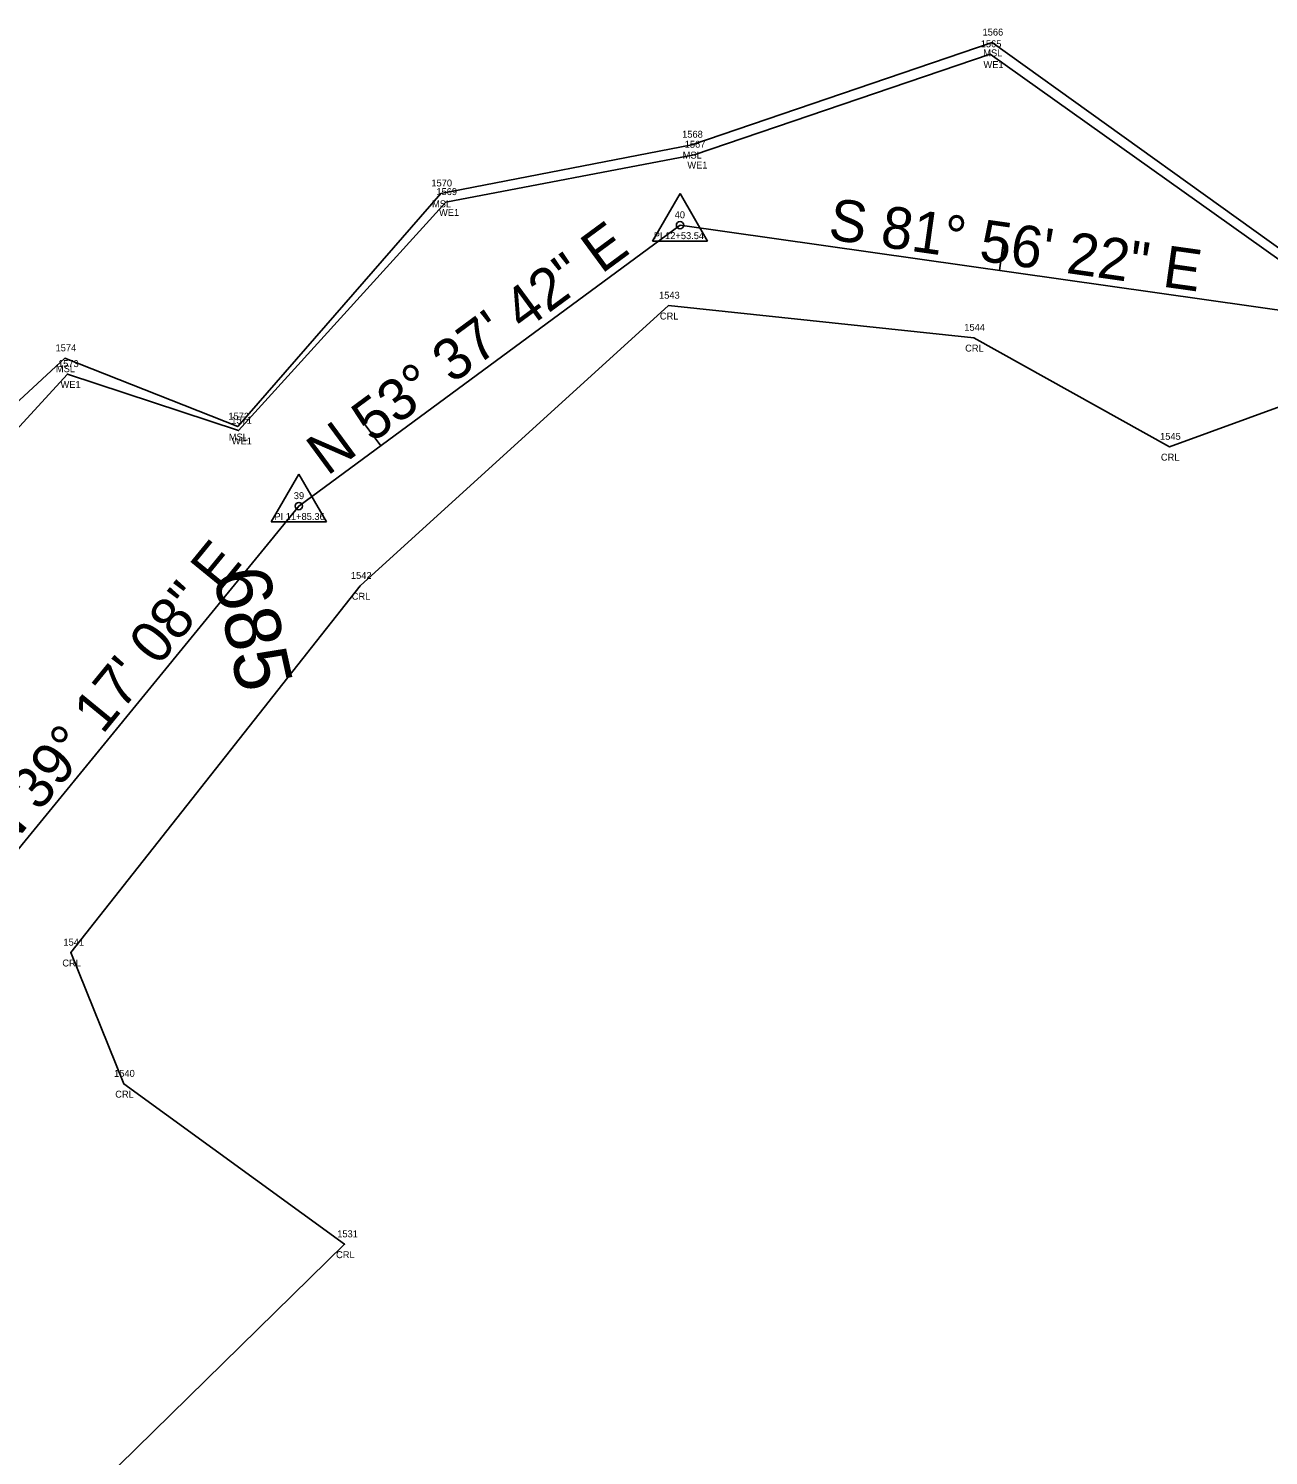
# Model space of a CAD drawing. Extents: x 2521558 to 2524785, y 882711 to 887632.
# Drawn here: x 2523844.7 to 2524023.3, y 885124.5 to 885330 of the extents above; entities that cross this region are included whole.
import ezdxf

# ---------------------------------------------------------------- set-up
doc = ezdxf.new("R2010")
doc.units = 0
for name, color, linetype in [('RD_EX_H2O', 7, 'Continuous'), ('RD_EX_H2O_txCode', 7, 'Continuous'), ('RD_EX_Misc', 7, 'Continuous'), ('RD_EX_Misc_txCode', 7, 'Continuous'), ('RD_HC_Cl', 7, 'Continuous'), ('RD_HC_Data', 7, 'Continuous'), ('RD_HC_Data_Tic', 7, 'Continuous'), ('RD_HC_TX_Sta50', 7, 'Continuous'), ('RD_HC_txCode', 7, 'Continuous'), ('RD_SMD_Locator', 7, 'Continuous')]:
    doc.layers.add(name, color=color, linetype=linetype)

msp = doc.modelspace()

# ---------------------------------------------------------------- linework, layer by layer
at = {"layer": 'RD_EX_H2O'}
for points in [[(2524064.86, 885165.15), (2524036.37, 885213.78), (2524057.22, 885252.72), (2524031.95, 885291.63), (2523983.25, 885326.3), (2523940.61, 885311.83), (2523904.84, 885305.01), (2523874.98, 885272.1), (2523850.32, 885280.24), (2523830.66, 885258.8), (2523826.93, 885206.61)], [(2523582.82, 884766.34), (2523598.11, 884856.98), (2523627.59, 884901.75), (2523623.76, 884928.28), (2523586.58, 884955.43), (2523600.94, 884974.12), (2523633.05, 884997.68), (2523679.17, 885037.05), (2523744.72, 885076.89), (2523769.38, 885099), (2523825.47, 885108.66), (2523825.47, 885108.66), (2523845.24, 885110.83), (2523890.25, 885154.93), (2523858.43, 885178.04), (2523850.81, 885196.93), (2523892.51, 885249.74), (2523936.89, 885290.09), (2523980.86, 885285.47), (2524009.06, 885269.77), (2524037.39, 885280.09)]]:
    msp.add_lwpolyline(points, dxfattribs=at)
at = {"layer": 'RD_EX_Misc'}
msp.add_lwpolyline([(2524066.31, 885165.35), (2524037.3, 885214.15), (2524057.95, 885253.07), (2524039.52, 885283.17), (2524032.92, 885292.57), (2523983.53, 885327.98), (2523940.24, 885313.27), (2523904.13, 885306.25), (2523874.86, 885272.67), (2523849.96, 885282.51), (2523827.65, 885261.93), (2523821.38, 885209.28)], dxfattribs=at)
at = {"layer": 'RD_HC_Cl'}
for p, q in [((2523883.66, 885261.23), (2523938.56, 885301.67)), ((2523938.56, 885301.67), (2524036.25, 885287.83)), ((2523836.11, 885203.1), (2523883.66, 885261.23))]:
    msp.add_line(p, q, dxfattribs=at)
at = {"layer": 'RD_HC_Data'}
for p, q in [((2523934.59, 885299.37), (2523938.56, 885306.25)), ((2523938.56, 885306.25), (2523942.53, 885299.37)), ((2523934.59, 885299.37), (2523942.53, 885299.37)), ((2523879.69, 885258.94), (2523883.66, 885265.82)), ((2523883.66, 885265.82), (2523887.63, 885258.94)), ((2523879.69, 885258.94), (2523887.63, 885258.94))]:
    msp.add_line(p, q, dxfattribs=at)
for centre in [(2523938.56, 885301.67), (2523883.66, 885261.23)]:
    msp.add_circle(centre, 0.529, dxfattribs=at)
at = {"layer": 'RD_HC_Data_Tic'}
for p, q in [((2523984.56, 885295.15), (2523985.12, 885299.11)), ((2523895.45, 885269.91), (2523893.08, 885273.13))]:
    msp.add_line(p, q, dxfattribs=at)
at = {"layer": 'RD_SMD_Locator'}
for centre in [(2523983.53, 885327.98), (2523983.25, 885326.3), (2523940.24, 885313.27), (2523940.61, 885311.83), (2523904.13, 885306.25), (2523904.84, 885305.01), (2523938.56, 885301.67), (2523936.89, 885290.09), (2523980.86, 885285.47), (2523849.96, 885282.51), (2523850.32, 885280.24), (2523874.86, 885272.67), (2523874.98, 885272.1), (2524009.06, 885269.77), (2523883.66, 885261.23), (2523892.51, 885249.74), (2523850.81, 885196.93), (2523858.43, 885178.04), (2523890.25, 885154.93)]:
    msp.add_circle(centre, 0.001, dxfattribs=at)

# ---------------------------------------------------------------- texts
at = {"layer": 'RD_EX_H2O_txCode'}
for s, p in [('1565', (2523981.88, 885327.3)), ('WE1', (2523982.27, 885324.3)), ('1567', (2523939.24, 885312.83)), ('WE1', (2523939.62, 885309.83)), ('1569', (2523903.47, 885306.01)), ('WE1', (2523903.85, 885303.01)), ('1543', (2523935.54, 885291.09)), ('CRL', (2523935.66, 885288.09)), ('1544', (2523979.51, 885286.47)), ('CRL', (2523979.63, 885283.47)), ('1573', (2523848.97, 885281.24)), ('WE1', (2523849.33, 885278.24)), ('1571', (2523873.92, 885273.1)), ('WE1', (2523874, 885270.1)), ('1545', (2524007.71, 885270.77)), ('CRL', (2524007.83, 885267.77)), ('1542', (2523891.16, 885250.74)), ('CRL', (2523891.28, 885247.74)), ('1541', (2523849.75, 885197.93)), ('CRL', (2523849.59, 885194.93)), ('1540', (2523857.05, 885179.04)), ('CRL', (2523857.21, 885176.04)), ('1531', (2523889.19, 885155.93)), ('CRL', (2523889.02, 885152.93))]:
    msp.add_text(s, height=1, dxfattribs=at).set_placement(p)
at = {"layer": 'RD_EX_Misc_txCode'}
for s, p in [('1566', (2523982.14, 885328.98)), ('MSL', (2523982.24, 885325.98)), ('1568', (2523938.87, 885314.27)), ('MSL', (2523938.95, 885311.27)), ('1570', (2523902.75, 885307.25)), ('MSL', (2523902.84, 885304.25)), ('1574', (2523848.61, 885283.51)), ('MSL', (2523848.67, 885280.51)), ('1572', (2523873.51, 885273.67)), ('MSL', (2523873.57, 885270.67))]:
    msp.add_text(s, height=1, dxfattribs=at).set_placement(p)
at = {"layer": 'RD_HC_Data'}
for s, rotation, p in [('S 81%%d 56\' 22" E', 351.9395, (2523959.76, 885299.67)), ('N 53%%d 37\' 42" E', 36.3717, (2523887.74, 885265.48)), ('N 39%%d 17\' 08" E', 50.7144, (2523841.2, 885210.9))]:
    msp.add_text(s, height=6, rotation=rotation, dxfattribs=at).set_placement(p)
at = {"layer": 'RD_HC_TX_Sta50'}
msp.add_text('685', height=8, rotation=282.4185, dxfattribs=at).set_placement((2523871.26, 885251.48))
at = {"layer": 'RD_HC_txCode'}
for s, p in [('40', (2523937.79, 885302.67)), ('PI 12+53.54', (2523934.78, 885299.67)), ('39', (2523882.93, 885262.23)), ('PI 11+85.36', (2523880.14, 885259.23))]:
    msp.add_text(s, height=1, dxfattribs=at).set_placement(p)

doc.saveas('drawing.dxf')
